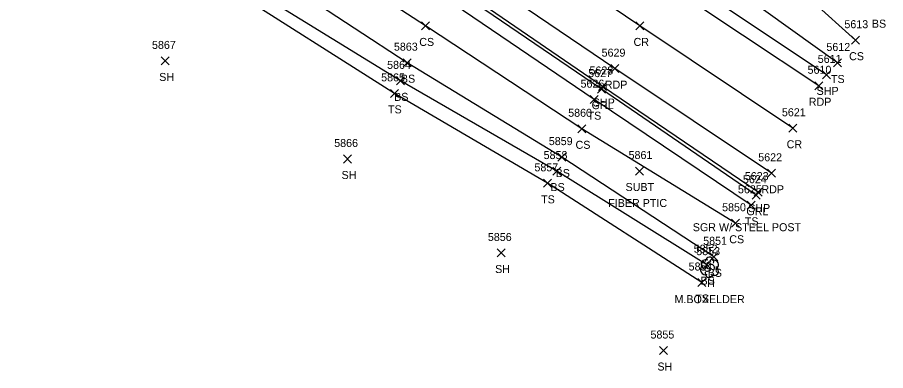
# Model space of a CAD drawing. Extents: x 1505656 to 1508446, y 700805 to 703031.
# Drawn here: x 1508137.1 to 1508354, y 700804.6 to 700892.9 of the extents above; entities that cross this region are included whole.
import ezdxf

# ---------------------------------------------------------------- set-up
doc = ezdxf.new("R2010")
doc.units = 0
for name, color, linetype in [('L_A', 7, 'Continuous'), ('L_C', 7, 'Continuous'), ('L_I', 7, 'Continuous'), ('L_TIC', 7, 'Continuous'), ('LELB', 7, 'Continuous'), ('LTD', 7, 'Continuous'), ('P_A', 7, 'Continuous'), ('P_I', 7, 'Continuous'), ('P_TIC', 7, 'Continuous'), ('PET', 7, 'Continuous'), ('PRC', 7, 'Continuous'), ('PSP', 7, 'Continuous'), ('R_A', 7, 'Continuous'), ('R_C', 7, 'Continuous'), ('R_I', 7, 'Continuous'), ('R_TIC', 7, 'Continuous'), ('RGR', 7, 'Continuous'), ('U_A', 7, 'Continuous'), ('U_C', 7, 'Continuous'), ('U_I', 7, 'Continuous'), ('U_TIC', 7, 'Continuous')]:
    doc.layers.add(name, color=color, linetype=linetype)

msp = doc.modelspace()

# ---------------------------------------------------------------- linework, layer by layer
at = {"layer": 'L_TIC'}
for points in [[(1508238.04, 700889.76), (1508240.04, 700891.76)], [(1508240.04, 700889.76), (1508238.04, 700891.76)], [(1508345.42, 700886.19), (1508347.42, 700888.19)], [(1508347.42, 700886.19), (1508345.42, 700888.19)], [(1508173.03, 700881.01), (1508175.03, 700883.01)], [(1508175.03, 700881.01), (1508173.03, 700883.01)], [(1508233.46, 700880.57), (1508235.46, 700882.57)], [(1508235.46, 700880.57), (1508233.46, 700882.57)], [(1508340.92, 700880.5), (1508342.92, 700882.5)], [(1508342.92, 700880.5), (1508340.92, 700882.5)], [(1508231.76, 700876.03), (1508233.76, 700878.03)], [(1508233.76, 700876.03), (1508231.76, 700878.03)], [(1508230.27, 700872.9), (1508232.27, 700874.9)], [(1508232.27, 700872.9), (1508230.27, 700874.9)], [(1508280.14, 700871.33), (1508282.14, 700873.33)], [(1508282.14, 700871.33), (1508280.14, 700873.33)], [(1508277.07, 700864.05), (1508279.07, 700866.05)], [(1508279.07, 700864.05), (1508277.07, 700866.05)], [(1508272.11, 700856.97), (1508274.11, 700858.97)], [(1508274.11, 700856.97), (1508272.11, 700858.97)], [(1508218.59, 700856.5), (1508220.59, 700858.5)], [(1508220.59, 700856.5), (1508218.59, 700858.5)], [(1508270.81, 700853.48), (1508272.81, 700855.48)], [(1508272.81, 700853.48), (1508270.81, 700855.48)], [(1508268.51, 700850.42), (1508270.51, 700852.42)], [(1508270.51, 700850.42), (1508268.51, 700852.42)], [(1508319.4, 700844.93), (1508321.4, 700846.93)], [(1508321.4, 700844.93), (1508319.4, 700846.93)], [(1508315.48, 700840.44), (1508317.48, 700842.44)], [(1508317.48, 700840.44), (1508315.48, 700842.44)], [(1508256.94, 700833.01), (1508258.94, 700835.01)], [(1508258.94, 700833.01), (1508256.94, 700835.01)], [(1508310.09, 700832.05), (1508312.09, 700834.05)], [(1508312.09, 700832.05), (1508310.09, 700834.05)], [(1508308.3, 700830.08), (1508310.3, 700832.08)], [(1508310.3, 700830.08), (1508308.3, 700832.08)], [(1508307.03, 700825.63), (1508309.03, 700827.63)], [(1508309.03, 700825.63), (1508307.03, 700827.63)], [(1508297.5, 700808.63), (1508299.5, 700810.63)], [(1508299.5, 700808.63), (1508297.5, 700810.63)]]:
    msp.add_lwpolyline(points, dxfattribs=at)
at = {"layer": 'LELB'}
for points in [[(1508341.92, 700881.5), (1508318.49, 700898.47), (1508297.5, 700911.93), (1508290.7, 700922.28), (1508289.39, 700937.94), (1508297.09, 700951.83), (1508308.03, 700965.67), (1508326.08, 700976.14)], [(1508320.4, 700845.93), (1508281.14, 700872.33), (1508222.89, 700912.02), (1508187.62, 700935.98), (1508155.8, 700957.09), (1508138.7, 700965.11)], [(1508316.48, 700841.44), (1508278.07, 700865.05), (1508239.04, 700890.76), (1508194.36, 700919.85), (1508152.86, 700952), (1508140.82, 700954.79), (1508132.27, 700953.56), (1508118.9, 700950.1), (1508105.54, 700945.9), (1508092.5, 700934.1), (1508084.21, 700930.56), (1508081.86, 700927.37), (1508080.22, 700924.62), (1508084.67, 700923.14), (1508097.36, 700925.85), (1508110.7, 700930.42), (1508126.08, 700933.28), (1508140.56, 700929.31)], [(1508311.09, 700833.05), (1508273.11, 700857.97), (1508234.46, 700881.57), (1508194.72, 700907.58), (1508150.5, 700935.57), (1508133.19, 700943.95), (1508120.99, 700942.53), (1508107.74, 700939), (1508092.96, 700931.94), (1508085.99, 700929.25), (1508084.94, 700925.48), (1508096.82, 700927.66), (1508109.54, 700933.15), (1508126.38, 700936.34), (1508141.97, 700932.45)], [(1508309.3, 700831.08), (1508271.81, 700854.48), (1508232.76, 700877.03), (1508190.65, 700903.02), (1508141.97, 700932.45)], [(1508308.03, 700826.63), (1508269.51, 700851.42), (1508231.27, 700873.9), (1508188.76, 700900.91), (1508140.56, 700929.31)], [(1508346.42, 700887.19), (1508324.65, 700906.98), (1508304.21, 700920.51)]]:
    msp.add_lwpolyline(points, dxfattribs=at)
at = {"layer": 'LTD'}
msp.add_line((1508309.94, 700830.47), (1508309.94, 700830.47), dxfattribs=at)
msp.add_line((1508309.94, 700830.47), (1508309.94, 700830.47), dxfattribs=at)
msp.add_arc((1508309.99, 700831.9), 1.05, 335.5272, 180.9563, dxfattribs=at)
for centre, major_axis, ratio, start_param, end_param in [((1508308.86, 700829.76), (0.58, -1.04), 0.959034, 3.141593, 6.283185), ((1508309.15, 700831.13), (1.21, -0.51), 0.895232, 1.570796, 4.712389), ((1508309.74, 700830.92), (-0.208, -0.792), 0.645439, 3.141593, 6.283185), ((1508310.44, 700830.3), (-0.5, 0.667), 0.989748, 3.141593, 6.283185), ((1508310.94, 700829.63), (-1.09, 0.79), 0.841452, 1.570796, 4.712389), ((1508310.99, 700831.05), (-1.14, -0.48), 0.949671, 1.570796, 4.712389), ((1508309.94, 700828.97), (0.26, 1.06), 0.942809, 1.570796, 4.712389), ((1508309.49, 700829.72), (-0.625, -0.083), 0.423636, 0, 3.141593)]:
    msp.add_ellipse(centre, major_axis=major_axis, ratio=ratio, start_param=start_param, end_param=end_param, dxfattribs=at)
at = {"layer": 'P_TIC'}
for points in [[(1508291.58, 700889.76), (1508293.58, 700891.76)], [(1508293.58, 700889.76), (1508291.58, 700891.76)], [(1508285.34, 700879.08), (1508287.34, 700881.08)], [(1508287.34, 700879.08), (1508285.34, 700881.08)], [(1508338.2, 700877.52), (1508340.2, 700879.52)], [(1508340.2, 700877.52), (1508338.2, 700879.52)], [(1508282.29, 700874.62), (1508284.29, 700876.62)], [(1508284.29, 700874.62), (1508282.29, 700876.62)], [(1508336.31, 700874.8), (1508338.31, 700876.8)], [(1508338.31, 700874.8), (1508336.31, 700876.8)], [(1508329.81, 700864.18), (1508331.81, 700866.18)], [(1508331.81, 700864.18), (1508329.81, 700866.18)], [(1508324.47, 700852.93), (1508326.47, 700854.93)], [(1508326.47, 700852.93), (1508324.47, 700854.93)], [(1508321.11, 700848.23), (1508323.11, 700850.23)], [(1508323.11, 700848.23), (1508321.11, 700850.23)]]:
    msp.add_lwpolyline(points, dxfattribs=at)
at = {"layer": 'PET'}
for points in [[(1508337.31, 700875.8), (1508299.12, 700901.22), (1508243.21, 700939.46), (1508171.95, 700987.77), (1508130.48, 701015.52), (1508098, 701037.64), (1508055.47, 701066.53), (1508022.23, 701089.23), (1507988.57, 701112.23), (1507963.26, 701129.32), (1507945.8, 701141.83), (1507902.27, 701172.19), (1507883.2, 701183.96), (1507860.24, 701201.06), (1507835.12, 701217.44), (1507805.58, 701238.78), (1507763.25, 701266.99), (1507728.86, 701291.36), (1507688.43, 701318.43), (1507655.64, 701340.89)], [(1508325.47, 700853.93), (1508286.34, 700880.08), (1508228.39, 700919.42), (1508193.53, 700942.69), (1508162.03, 700964.2), (1508126.36, 700988.76), (1508069.26, 701027.69), (1508039.88, 701046.84), (1507982.91, 701086.28), (1507949.88, 701109.29), (1507927.44, 701124.58), (1507885.02, 701153.86), (1507843.8, 701182.01), (1507811.49, 701204.8), (1507770.51, 701232.43), (1507732.44, 701258.92), (1507681.2, 701293.35)]]:
    msp.add_lwpolyline(points, dxfattribs=at)
at = {"layer": 'PRC'}
msp.add_lwpolyline([(1508330.81, 700865.18), (1508292.58, 700890.76), (1508235.81, 700929.21), (1508200.17, 700953), (1508165.62, 700976.67), (1508123.91, 701005.48), (1508090.88, 701028.02), (1508048, 701056.52), (1508015.22, 701078.96), (1507981.58, 701102.27), (1507956.81, 701119), (1507935.36, 701133.83), (1507892.74, 701162.9), (1507856.87, 701187.72), (1507818.46, 701214.03), (1507776.64, 701243.14), (1507739.63, 701268.4), (1507687.66, 701303.5)], dxfattribs=at)
at = {"layer": 'PSP'}
for points in [[(1508339.2, 700878.52), (1508300.65, 700904.32), (1508290.66, 700911.25), (1508285.71, 700920.13), (1508246.94, 700946.03), (1508214.54, 700968.68), (1508208.31, 700968.43), (1508200.27, 700972.31), (1508174.14, 700990.25), (1508132.47, 701018.55), (1508100.45, 701040.48), (1508057.36, 701069.9), (1508024.07, 701092.52), (1507991.15, 701114.56), (1507965.56, 701132.67), (1507948.13, 701145), (1507904.26, 701176.52), (1507885.27, 701189.48), (1507863.62, 701204.84), (1507839.06, 701222.13), (1507808.57, 701243.06), (1507766.97, 701271.37), (1507732.08, 701295.24), (1507690.9, 701323.18)], [(1508322.11, 700849.23), (1508283.29, 700875.62), (1508225.23, 700915.4), (1508190.18, 700938.93), (1508158.85, 700960.02), (1508133.58, 700977.43), (1508108.68, 700994.35), (1508066.55, 701022.65), (1508035.75, 701043.71), (1507979.02, 701080.76), (1507948.09, 701102.19), (1507924.34, 701119.43), (1507882.16, 701148.7), (1507840.1, 701177.09), (1507807.52, 701199.39), (1507768.58, 701225.94), (1507728.95, 701254.66), (1507678.68, 701288.49)]]:
    msp.add_lwpolyline(points, dxfattribs=at)
at = {"layer": 'R_TIC'}
for points in [[(1508281.99, 700873.96), (1508283.99, 700875.96)], [(1508283.99, 700873.96), (1508281.99, 700875.96)], [(1508320.64, 700847.45), (1508322.64, 700849.45)], [(1508322.64, 700847.45), (1508320.64, 700849.45)]]:
    msp.add_lwpolyline(points, dxfattribs=at)
at = {"layer": 'RGR'}
msp.add_lwpolyline([(1508321.64, 700848.45), (1508282.99, 700874.96), (1508224.72, 700914.71), (1508189.84, 700938.49), (1508158.41, 700959.67), (1508127.22, 700975.17)], dxfattribs=at)
at = {"layer": 'U_TIC'}
for points in [[(1508291.51, 700853.5), (1508293.51, 700855.5)], [(1508293.51, 700853.5), (1508291.51, 700855.5)]]:
    msp.add_lwpolyline(points, dxfattribs=at)

# ---------------------------------------------------------------- texts
at = {"layer": 'L_A'}
for s, p in [('BS', (1508350.54, 700890.32)), ('CS', (1508237.48, 700885.76)), ('CS', (1508344.86, 700882.19)), ('SH', (1508172.52, 700877.01)), ('BS', (1508232.9, 700876.57)), ('TS', (1508340.33, 700876.5)), ('BS', (1508231.2, 700872.03)), ('TS', (1508229.68, 700868.9)), ('TS', (1508279.54, 700867.33)), ('CS', (1508276.52, 700860.05)), ('SH', (1508218.08, 700852.5)), ('BS', (1508271.55, 700852.97)), ('BS', (1508270.25, 700849.48)), ('TS', (1508267.92, 700846.42)), ('TS', (1508318.81, 700840.93)), ('CS', (1508314.92, 700836.44)), ('SH', (1508256.43, 700829.01)), ('BS', (1508309.53, 700828.05)), ('BS', (1508307.74, 700826.08)), ('H', (1508309.38, 700825.47)), ('TS', (1508306.44, 700821.63)), ('SH', (1508296.98, 700804.63))]:
    msp.add_text(s, height=2, dxfattribs=at).set_placement(p)
at = {"layer": 'L_C'}
msp.add_text('M.BOXELDER', height=2, dxfattribs=at).set_placement((1508301.24, 700821.47))
at = {"layer": 'L_I'}
for s, p in [('5613', (1508343.68, 700890.19)), ('5867', (1508170.72, 700885.01)), ('5863', (1508231.15, 700884.57)), ('5612', (1508339.18, 700884.5)), ('5864', (1508229.45, 700880.03)), ('5865', (1508227.96, 700876.9)), ('5626', (1508277.77, 700875.33)), ('5860', (1508274.68, 700868.05)), ('5859', (1508269.84, 700860.97)), ('5866', (1508216.23, 700860.5)), ('5858', (1508268.55, 700857.48)), ('5857', (1508266.25, 700854.42)), ('5625', (1508317.09, 700848.93)), ('5850', (1508313.13, 700844.44)), ('5856', (1508254.62, 700837.01)), ('5851', (1508308.4, 700836.05)), ('5852', (1508306.04, 700834.08)), ('5853', (1508306.68, 700833.47)), ('5854', (1508304.77, 700829.63)), ('5855', (1508295.24, 700812.63))]:
    msp.add_text(s, height=2, dxfattribs=at).set_placement(p)
at = {"layer": 'P_A'}
for s, p in [('CR', (1508291.01, 700885.76)), ('RDP', (1508283.83, 700875.08)), ('SHP', (1508336.73, 700873.52)), ('SHP', (1508280.83, 700870.62)), ('RDP', (1508334.79, 700870.8)), ('CR', (1508329.25, 700860.18)), ('RDP', (1508322.96, 700848.93)), ('SHP', (1508319.64, 700844.23))]:
    msp.add_text(s, height=2, dxfattribs=at).set_placement(p)
at = {"layer": 'P_I'}
for s, p in [('5629', (1508283.03, 700883.08)), ('5611', (1508337.02, 700881.52)), ('5628', (1508279.99, 700878.62)), ('5610', (1508334.48, 700878.8)), ('5621', (1508328.07, 700868.18)), ('5622', (1508322.16, 700856.93)), ('5623', (1508318.8, 700852.23))]:
    msp.add_text(s, height=2, dxfattribs=at).set_placement(p)
at = {"layer": 'R_A'}
for p in [(1508280.53, 700869.96), (1508319.19, 700843.45)]:
    msp.add_text('GRL', height=2, dxfattribs=at).set_placement(p)
at = {"layer": 'R_C'}
msp.add_text('SGR W/ STEEL POST', height=2, dxfattribs=at).set_placement((1508305.81, 700839.45))
at = {"layer": 'R_I'}
for s, p in [('5627', (1508279.68, 700877.96)), ('5624', (1508318.34, 700851.45))]:
    msp.add_text(s, height=2, dxfattribs=at).set_placement(p)
at = {"layer": 'U_A'}
msp.add_text('SUBT', height=2, dxfattribs=at).set_placement((1508289.01, 700849.5))
at = {"layer": 'U_C'}
msp.add_text('FIBER PTIC', height=2, dxfattribs=at).set_placement((1508284.68, 700845.5))
at = {"layer": 'U_I'}
msp.add_text('5861', height=2, dxfattribs=at).set_placement((1508289.77, 700857.5))

doc.saveas('drawing.dxf')
